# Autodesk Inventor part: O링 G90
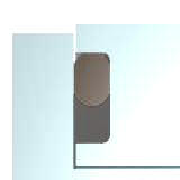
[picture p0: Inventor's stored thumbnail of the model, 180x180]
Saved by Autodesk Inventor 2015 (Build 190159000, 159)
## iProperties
IsCustomPart: 1
Created: 2012-02
Part Number: O링 G90
Material: 고무
Description: O-링
Document SubType Name: Modeling
Standard: JIS B 2406
Designer: mdu-01
Standards Organization: JIS
Language: ko-KR
Size Designation: G 90
Categories: <MemberInstance><Categories><Category DisplayName="샤프트 부품" InternalName="7f7aeb1f-a693-4053-b835-cee3144e0d98" Mnemonic="SHFT"><Category DisplayName="실링" Intern
Density: 0.93 g/cm^3
Appearance: 고무 - 검은색 - 버전 1.1
Author: mdu-01
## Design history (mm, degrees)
revolve "본체" stored, may be unused: angle "d7" = 90 deg
body "Solid1"
sketch "스케치1"
  geometry: L1 (0, 45.95)-(-1.2, 45.95); L2 (-1.2, 45.95)-(-1.2, 44.4); L3 (0, 44.969)-(0, 45.95); L4 (-1.2, 45.95)-(-1.2, 47.5); L5 (0, 46.931)-(0, 45.95) reference; L6 (-2.4, 46.931)-(-2.4, 45.95); L7 (-2.4, 44.969)-(-2.4, 45.95); L8 (-1.2, 45.95)-(-1.2, 47.5); L9 (0, 17.106)-(0, -2.851) reference; L10 (-2, 0)-(1, 0) reference; L11 (-2.62, 0)-(1.603, 0) reference; A1 r 1.55 centre (-1.2, 45.95) between (-1.2, 44.4) and (0, 44.969); A2 r 1.55 centre (-1.2, 45.95) between (0, 46.931) and (-1.2, 47.5); A3 r 1.55 centre (-1.2, 45.95) between (-1.2, 47.5) and (-2.4, 46.931); A4 r 1.55 centre (-1.2, 45.95) between (-2.4, 44.969) and (-1.2, 44.4)
  constraints: 18 end point, 8 point on circle, 5 symmetric about line, 4 centre point, 2 horizontal, 2 perpendicular, 1 parallel, 1 vertical, 9 other
  dimensions: "d0" = 1.55 radius of A1 (= 0.5 x QDM); "d1" = 1.2 distance between parallel lines of L9 L2 (= 0.5 x NTOR); "d2" = 95 diameter of L4.end L10 (= NDO1)
other parameters: "QDM" = 3.1 [user parameter; used in 1 equation term], "NTOR" = 2.4 [user parameter; used in 1 equation term], "NDO1" = 95 [user parameter; used in 1 equation term], "d3" = 0, "d4" = 0, "d5" = 0, "R2" = 0.2 [user parameter], "SD1" = 89.4 [user parameter], "R1" = 0.7 [user parameter], "NB1" = 4.1 [user parameter]
